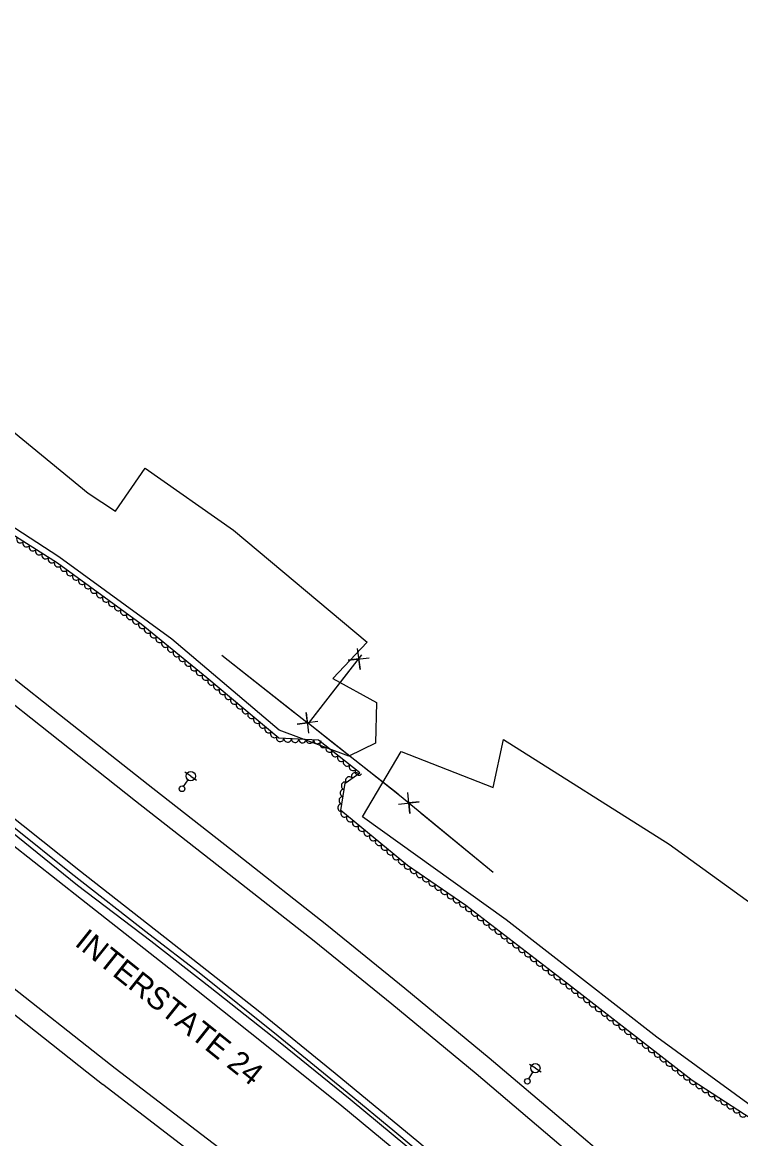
# Model space of a CAD drawing. Extents: x 1746719 to 1766531, y 631721 to 662391.
# Drawn here: x 1757033 to 1757419, y 645333 to 645932 of the extents above; entities that cross this region are included whole.
import ezdxf

# ---------------------------------------------------------------- set-up
doc = ezdxf.new("R2010")
doc.units = 0
for name, color, linetype in [('SURVEY - AERIAL SURVEY - Photo Control - Points - Elevations', 7, 'Continuous'), ('SURVEY - AERIAL SURVEY - Photo Control - Points - Locators', 7, 'Continuous'), ('SURVEY - AERIAL SURVEY - Photo Control - Points - Numbers', 7, 'Continuous'), ('SURVEY - AERIAL SURVEY - Photo Control with Text', 7, 'Continuous'), ('SURVEY - CENTERLINE - Existing Roads - Development', 7, 'Continuous'), ('SURVEY - CENTERLINE - Existing Roads Curve Text', 7, 'Continuous'), ('SURVEY - CONTROL - Points - Numbers', 7, 'Continuous'), ('SURVEY - DRAINAGE - Area Shapes - Points - Locators', 7, 'Continuous')]:
    doc.layers.add(name, color=color, linetype=linetype)

msp = doc.modelspace()

# ---------------------------------------------------------------- linework, layer by layer
at = {"layer": 'SURVEY - AERIAL SURVEY - Photo Control - Points - Elevations'}
msp.add_line((1757076.66, 645361.73), (1757315.45, 645178.97), dxfattribs=at)
for points in [[(1756502.93, 645947.08), (1756549.13, 645902.1), (1756590.66, 645862.49), (1756632.17, 645824.37), (1756672.33, 645787.7), (1756715.43, 645749.13), (1756757.44, 645711.96), (1756801.04, 645674.8), (1756840.91, 645641.49), (1756876.29, 645612.14), (1756908.61, 645585.97), (1756944.66, 645556.76), (1756985.81, 645524.02), (1757027.09, 645491.2), (1757065.26, 645461.08), (1757112.18, 645424.18), (1757155.78, 645389.59), (1757203.98, 645351.12), (1757243.49, 645318.34), (1757284.79, 645283.57), (1757319.72, 645253.76)], [(1756520.19, 645945.65), (1756555.23, 645911.97), (1756593.2, 645875.5), (1756635.63, 645835.8), (1756670.53, 645804), (1756698.49, 645778.91), (1756734.27, 645747.18), (1756769.97, 645716.22), (1756811.01, 645681.05), (1756852.73, 645645.89), (1756895.72, 645610.43), (1756935.63, 645578.29), (1756973.61, 645548.11), (1757013.49, 645516.71), (1757064.64, 645476.21), (1757112.5, 645438.8), (1757160.2, 645401.29), (1757201.56, 645367.78), (1757246.35, 645330.65), (1757286.95, 645296.25), (1757329.1, 645260.45)], [(1756421.75, 645942.95), (1756460.91, 645904.24), (1756507.5, 645858.9), (1756549.66, 645818.68), (1756591.65, 645780.12), (1756632.09, 645743.18), (1756675.55, 645704.31), (1756718.1, 645666.66), (1756762.34, 645628.94), (1756802.52, 645595.38), (1756838.25, 645565.73), (1756870.85, 645539.34), (1756907.09, 645509.98), (1756948.46, 645477.06), (1756989.84, 645444.17), (1757028.13, 645413.95), (1757074.99, 645377.09), (1757083.35, 645370.46)], [(1756413.97, 645935.17), (1756453.21, 645896.39), (1756499.86, 645850.98), (1756542.14, 645810.65), (1756584.22, 645772.01), (1756624.72, 645735.02), (1756668.23, 645696.09), (1756710.88, 645658.35), (1756755.25, 645620.53), (1756795.48, 645586.92), (1756831.28, 645557.22), (1756863.93, 645530.79), (1756900.2, 645501.4), (1756941.62, 645468.45), (1756983.01, 645435.55), (1757021.32, 645405.31), (1757068.17, 645368.46), (1757076.51, 645361.84)], [(1756845.35, 645729.27), (1756890.52, 645691.2), (1756932.99, 645656.16), (1756972.48, 645624.36), (1757010.21, 645594.39), (1757050.05, 645563.01), (1757101.12, 645522.58), (1757148.9, 645485.23), (1757197, 645447.4), (1757238.96, 645413.41), (1757284.25, 645375.87), (1757325.12, 645341.24), (1757367.29, 645305.42)], [(1756838.26, 645720.86), (1756883.47, 645682.75), (1756926.04, 645647.63), (1756965.61, 645615.77), (1757003.39, 645585.76), (1757043.23, 645554.38), (1757094.32, 645513.93), (1757142.11, 645476.57), (1757190.14, 645438.8), (1757231.99, 645404.9), (1757277.18, 645367.44), (1757318, 645332.85), (1757360.17, 645297.04)]]:
    msp.add_lwpolyline(points, dxfattribs=at)
at = {"layer": 'SURVEY - AERIAL SURVEY - Photo Control - Points - Locators'}
for points in [[(1757028.72, 645711.99), (1757068.92, 645678.98), (1757083.51, 645669.47), (1757099.43, 645692.47), (1757146.9, 645659.13), (1757218.68, 645599.14), (1757200.18, 645579.64), (1757223.75, 645566.6), (1757223.16, 645544.82), (1757208.75, 645537.85), (1757171.36, 645551.81), (1757113.71, 645600.61), (1757053.16, 645644.94), (1757025.85, 645662.51)], [(1757291.94, 645546.75), (1757380.93, 645490.61), (1757481.61, 645417.77), (1757526.95, 645381.86), (1757448.22, 645333.19), (1757374.17, 645387.09), (1757293.32, 645450.07), (1757216.12, 645505.27), (1757236.85, 645540.38), (1757286.25, 645521.08), (1757291.94, 645546.75)]]:
    msp.add_lwpolyline(points, dxfattribs=at)
at = {"layer": 'SURVEY - AERIAL SURVEY - Photo Control - Points - Numbers'}
for points in [[(1756521.89, 645935.44), (1756561.39, 645897.49), (1756596.47, 645864.07), (1756637.95, 645824.65), (1756680.19, 645787.47), (1756717.81, 645753.34), (1756753.33, 645722.42), (1756799.28, 645683.57), (1756839.74, 645649.38), (1756877.79, 645617.19), (1756917.49, 645584.46), (1756948.89, 645559.79), (1756986.82, 645528.9), (1757027.26, 645497.56), (1757063.14, 645468.7), (1757102.43, 645438.73), (1757134.3, 645413.92), (1757171.9, 645384.09), (1757209.5, 645353.81), (1757247.4, 645322.51), (1757278.39, 645295.74), (1757314.93, 645264.45), (1757323.62, 645256.72)], [(1756547.68, 645914.17), (1756587.71, 645875.44), (1756625.65, 645839.47), (1756655.57, 645811.91), (1756695.99, 645775.64), (1756730.4, 645745.48), (1756771.16, 645710.28), (1756805.22, 645681.09), (1756845.17, 645647.77), (1756885.53, 645613.73), (1756927.96, 645579.65), (1756961.93, 645552.61), (1756993.97, 645527), (1757028.08, 645500.44), (1757059.79, 645475.07), (1757101.49, 645442.54), (1757128.52, 645421.75), (1757170.88, 645387.78), (1757207.89, 645357.47), (1757233.48, 645336.47), (1757257.7, 645316.15), (1757285.19, 645293.46), (1757314.32, 645268.1), (1757325.84, 645258.19)]]:
    msp.add_lwpolyline(points, dxfattribs=at)
at = {"layer": 'SURVEY - AERIAL SURVEY - Photo Control with Text'}
msp.add_lwpolyline([(1757435.56, 645336.21), (1757393.26, 645363.83), (1757325.18, 645416.52), (1757271.74, 645457.62), (1757240.37, 645479.15), (1757204.56, 645508.64), (1757206.91, 645523.44), (1757214.81, 645528.99), (1757192.59, 645546.41), (1757171.28, 645547.58), (1757132.62, 645579.93), (1757097.24, 645608.79), (1757052.39, 645641.54), (1757022.55, 645660.45), (1756989.65, 645695.77), (1756930.89, 645730.56), (1756898.03, 645745.84), (1756864.73, 645788.87), (1756847.34, 645805.21), (1756825.4, 645807.32), (1756776.27, 645858.62), (1756725.31, 645897.06), (1756695.58, 645927.68), (1756681.41, 645952.8)], dxfattribs=at)
for centre, major_axis in [((1757032.36, 645654.24), (-1.69, 1.07)), ((1757035.73, 645652.09), (-1.69, 1.07)), ((1757039.11, 645649.95), (-1.69, 1.07)), ((1757042.49, 645647.81), (-1.69, 1.07)), ((1757045.87, 645645.67), (-1.69, 1.07)), ((1757049.25, 645643.53), (-1.69, 1.07)), ((1757052.62, 645641.37), (-1.62, 1.18)), ((1757055.85, 645639.01), (-1.62, 1.18)), ((1757059.08, 645636.65), (-1.62, 1.18)), ((1757062.31, 645634.29), (-1.62, 1.18)), ((1757065.54, 645631.94), (-1.62, 1.18)), ((1757068.77, 645629.58), (-1.62, 1.18)), ((1757072, 645627.22), (-1.62, 1.18)), ((1757075.23, 645624.86), (-1.62, 1.18)), ((1757078.46, 645622.5), (-1.62, 1.18)), ((1757081.69, 645620.14), (-1.62, 1.18)), ((1757084.92, 645617.78), (-1.62, 1.18)), ((1757088.15, 645615.42), (-1.62, 1.18)), ((1757091.38, 645613.06), (-1.62, 1.18)), ((1757094.61, 645610.7), (-1.62, 1.18)), ((1757097.82, 645608.31), (-1.55, 1.26)), ((1757100.92, 645605.79), (-1.55, 1.26)), ((1757104.02, 645603.26), (-1.55, 1.26)), ((1757107.12, 645600.73), (-1.55, 1.26)), ((1757110.22, 645598.2), (-1.55, 1.26)), ((1757113.32, 645595.68), (-1.55, 1.26)), ((1757116.42, 645593.15), (-1.55, 1.26)), ((1757119.52, 645590.62), (-1.55, 1.26)), ((1757122.62, 645588.09), (-1.55, 1.26)), ((1757125.72, 645585.56), (-1.55, 1.26)), ((1757128.82, 645583.04), (-1.55, 1.26)), ((1757131.92, 645580.51), (-1.55, 1.26)), ((1757134.99, 645577.95), (-1.53, 1.28)), ((1757138.06, 645575.38), (-1.53, 1.28)), ((1757141.13, 645572.82), (-1.53, 1.28)), ((1757144.19, 645570.25), (-1.53, 1.28)), ((1757147.26, 645567.68), (-1.53, 1.28)), ((1757150.33, 645565.11), (-1.53, 1.28)), ((1757153.4, 645562.55), (-1.53, 1.28)), ((1757156.46, 645559.98), (-1.53, 1.28)), ((1757159.53, 645557.41), (-1.53, 1.28)), ((1757162.6, 645554.84), (-1.53, 1.28)), ((1757165.66, 645552.28), (-1.53, 1.28)), ((1757168.73, 645549.71), (-1.53, 1.28)), ((1757171.96, 645547.54), (-2, 0.11)), ((1757175.95, 645547.32), (-2, 0.11)), ((1757179.94, 645547.1), (-2, 0.11)), ((1757183.94, 645546.88), (-2, 0.11)), ((1757187.93, 645546.67), (-2, 0.11)), ((1757191.93, 645546.45), (-2, 0.11)), ((1757195.21, 645544.35), (-1.57, 1.23)), ((1757198.36, 645541.88), (-1.57, 1.23)), ((1757201.51, 645539.41), (-1.57, 1.23)), ((1757204.66, 645536.95), (-1.57, 1.23)), ((1757207.8, 645534.48), (-1.57, 1.23)), ((1757210.95, 645532.01), (-1.57, 1.23)), ((1757214.1, 645529.54), (-1.57, 1.23)), ((1757209, 645524.91), (1.64, 1.15)), ((1757212.27, 645527.2), (1.64, 1.15)), ((1757206.06, 645518.06), (0.31, 1.98)), ((1757206.68, 645522.01), (0.31, 1.98)), ((1757205.43, 645514.11), (0.31, 1.98)), ((1757204.8, 645510.16), (0.31, 1.98)), ((1757206.46, 645507.07), (-1.54, 1.27)), ((1757209.55, 645504.53), (-1.54, 1.27)), ((1757212.64, 645501.99), (-1.54, 1.27)), ((1757215.73, 645499.44), (-1.54, 1.27)), ((1757218.81, 645496.9), (-1.54, 1.27)), ((1757221.9, 645494.36), (-1.54, 1.27)), ((1757224.99, 645491.82), (-1.54, 1.27)), ((1757228.08, 645489.27), (-1.54, 1.27)), ((1757231.17, 645486.73), (-1.54, 1.27)), ((1757234.25, 645484.19), (-1.54, 1.27)), ((1757237.34, 645481.65), (-1.54, 1.27)), ((1757240.43, 645479.11), (-1.65, 1.13)), ((1757243.73, 645476.85), (-1.65, 1.13)), ((1757247.03, 645474.58), (-1.65, 1.13)), ((1757250.33, 645472.32), (-1.65, 1.13)), ((1757253.63, 645470.06), (-1.65, 1.13)), ((1757256.92, 645467.79), (-1.65, 1.13)), ((1757260.22, 645465.53), (-1.65, 1.13)), ((1757263.52, 645463.26), (-1.65, 1.13)), ((1757266.82, 645461), (-1.65, 1.13)), ((1757270.12, 645458.74), (-1.65, 1.13)), ((1757273.35, 645456.38), (-1.59, 1.22)), ((1757276.52, 645453.95), (-1.59, 1.22)), ((1757279.69, 645451.51), (-1.59, 1.22)), ((1757282.86, 645449.07), (-1.59, 1.22)), ((1757286.03, 645446.63), (-1.59, 1.22)), ((1757289.2, 645444.19), (-1.59, 1.22)), ((1757292.37, 645441.75), (-1.59, 1.22)), ((1757295.54, 645439.31), (-1.59, 1.22)), ((1757298.71, 645436.87), (-1.59, 1.22)), ((1757301.88, 645434.44), (-1.59, 1.22)), ((1757305.05, 645432), (-1.59, 1.22)), ((1757308.22, 645429.56), (-1.59, 1.22)), ((1757311.39, 645427.12), (-1.59, 1.22)), ((1757314.57, 645424.68), (-1.59, 1.22)), ((1757317.74, 645422.24), (-1.59, 1.22)), ((1757320.91, 645419.8), (-1.59, 1.22)), ((1757324.08, 645417.36), (-1.59, 1.22)), ((1757327.24, 645414.92), (-1.58, 1.22)), ((1757330.41, 645412.47), (-1.58, 1.22)), ((1757333.57, 645410.02), (-1.58, 1.22)), ((1757336.73, 645407.57), (-1.58, 1.22)), ((1757339.9, 645405.13), (-1.58, 1.22)), ((1757343.06, 645402.68), (-1.58, 1.22)), ((1757346.22, 645400.23), (-1.58, 1.22)), ((1757349.39, 645397.78), (-1.58, 1.22)), ((1757352.55, 645395.33), (-1.58, 1.22)), ((1757355.71, 645392.89), (-1.58, 1.22)), ((1757358.88, 645390.44), (-1.58, 1.22)), ((1757362.04, 645387.99), (-1.58, 1.22)), ((1757365.2, 645385.54), (-1.58, 1.22)), ((1757368.37, 645383.09), (-1.58, 1.22)), ((1757371.53, 645380.64), (-1.58, 1.22)), ((1757374.69, 645378.2), (-1.58, 1.22)), ((1757377.85, 645375.75), (-1.58, 1.22)), ((1757381.02, 645373.3), (-1.58, 1.22)), ((1757384.18, 645370.85), (-1.58, 1.22)), ((1757387.34, 645368.4), (-1.58, 1.22)), ((1757390.51, 645365.95), (-1.58, 1.22)), ((1757393.7, 645363.54), (-1.67, 1.09)), ((1757397.05, 645361.35), (-1.67, 1.09)), ((1757400.39, 645359.17), (-1.67, 1.09)), ((1757403.74, 645356.98), (-1.67, 1.09)), ((1757407.09, 645354.79), (-1.67, 1.09)), ((1757410.44, 645352.61), (-1.67, 1.09)), ((1757413.79, 645350.42), (-1.67, 1.09)), ((1757417.14, 645348.24), (-1.67, 1.09)), ((1757420.49, 645346.05), (-1.67, 1.09))]:
    msp.add_ellipse(centre, major_axis=major_axis, ratio=0.940188, start_param=0, end_param=3.141593, dxfattribs=at)
at = {"layer": 'SURVEY - CENTERLINE - Existing Roads - Development'}
for p, q in [((1757120.1, 645521.6), (1757122.5, 645525.11)), ((1757123.92, 645527.17), (1757120.82, 645529.29)), ((1757123.92, 645527.17), (1757127.01, 645525.05)), ((1757309, 645370.41), (1757305.79, 645372.36)), ((1757309, 645370.41), (1757312.2, 645368.46)), ((1757305.5, 645364.64), (1757307.7, 645368.27))]:
    msp.add_line(p, q, dxfattribs=at)
for centre, radius in [((1757123.92, 645527.17), 2.5), ((1757119.25, 645520.37), 1.5), ((1757309, 645370.41), 2.5), ((1757304.72, 645363.36), 1.5)]:
    msp.add_circle(centre, radius, dxfattribs=at)
at = {"layer": 'SURVEY - CENTERLINE - Existing Roads Curve Text'}
for points in [[(1757140.6, 645592.14), (1757187.25, 645555.36)], [(1757140.6, 645592.14), (1757179.86, 645561.18)], [(1757286.25, 645475.37), (1757236.01, 645516.8), (1757187.25, 645555.36), (1757215.73, 645592.32)], [(1757213.35, 645595.61), (1757214.86, 645584.47), (1757214.14, 645590.08), (1757208.53, 645589.36), (1757219.68, 645590.73)], [(1757198.84, 645546.19), (1757187.25, 645555.36), (1757208.75, 645583.25)], [(1757192.17, 645556.45), (1757181.01, 645555.05), (1757186.63, 645555.72), (1757185.97, 645561.34), (1757187.22, 645550.16)], [(1757235.24, 645517.41), (1757198.84, 645546.19)], [(1757235.47, 645512.19), (1757246.66, 645513.33), (1757241.03, 645512.79), (1757241.57, 645507.16), (1757240.56, 645518.36)], [(1757286.25, 645475.37), (1757247.67, 645507.18)]]:
    msp.add_lwpolyline(points, dxfattribs=at)
at = {"layer": 'SURVEY - DRAINAGE - Area Shapes - Points - Locators'}
msp.add_line((1757083.35, 645370.46), (1757322.14, 645187.71), dxfattribs=at)

# ---------------------------------------------------------------- texts
at = {"layer": 'SURVEY - CONTROL - Points - Numbers'}
msp.add_text('INTERSTATE 24', height=12, rotation=321.40723, dxfattribs=at).set_placement((1757061.08, 645436.61))

doc.saveas('drawing.dxf')
